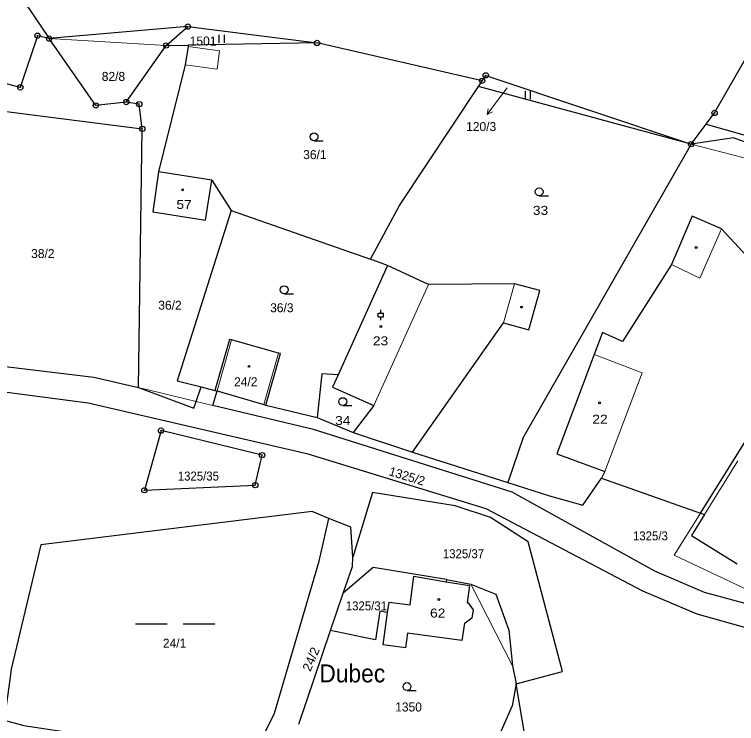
# Model space of a CAD drawing. Extents: x -872229 to -869198, y -1075981 to -1074329.
# Drawn here: x -871061.1 to -870924.3, y -1075218 to -1075083.8 of the extents above; entities that cross this region are included whole.
import ezdxf
from ezdxf.enums import TextEntityAlignment as Align

# ---------------------------------------------------------------- set-up
doc = ezdxf.new("R2010")
doc.units = 0
doc.header["$LTSCALE"] = 0.68
for name, color, linetype, lineweight in [('1', 7, 'Continuous', 25), ('3', 7, 'Continuous', 25), ('4', 7, 'Continuous', 13), ('5', 7, 'Continuous', 25), ('7', 7, 'Continuous', 13), ('8', 7, 'Continuous', 25)]:
    doc.layers.add(name, color=color, linetype=linetype, lineweight=lineweight)
doc.layers.add('2', color=7, linetype='Continuous')

msp = doc.modelspace()

# ---------------------------------------------------------------- linework, layer by layer
at = {"layer": '1'}
for p, q in [((-871028.23, -1075086.09), (-871054.49, -1075088.37)), ((-871028.23, -1075086.09), (-871003.76, -1075089.18)), ((-871032.34, -1075089.67), (-871028.14, -1075089.6)), ((-870932.92, -1075108.35), (-870973.2, -1075097.45)), ((-871023.7, -1075115.19), (-871033.76, -1075113.61)), ((-870990.4, -1075131.32), (-870993.62, -1075130.11)), ((-870990.4, -1075131.32), (-870999.76, -1075152)), ((-871023.09, -1075154.96), (-871022.7, -1075155.06)), ((-871013.43, -1075157.73), (-871003.73, -1075160.06)), ((-871003.73, -1075160.06), (-870996.9, -1075162.9)), ((-870985.66, -1075166.64), (-870967.62, -1075172.38)), ((-870979.23, -1075190.74), (-870979.29, -1075191.16))]:
    msp.add_line(p, q, dxfattribs=at)
for points in [[(-871096.99, -1075058.79), (-871086.45, -1075041.13), (-871054.49, -1075088.37)], [(-870930.06, -1075104.56), (-870928.47, -1075102.44), (-870911.59, -1075072.86)], [(-871039.89, -1075100.38), (-871032.34, -1075089.67), (-871028.23, -1075086.09)], [(-871054.49, -1075088.37), (-871056.71, -1075087.82), (-871059.95, -1075097.6), (-871082.7, -1075091.52), (-871084.87, -1075101.96), (-871097.87, -1075101.74), (-871098.57, -1075150.11)], [(-871039.89, -1075100.38), (-871045.65, -1075101.02), (-871054.49, -1075088.37)], [(-870930.06, -1075104.56), (-870893.7, -1075114.82), (-870892.44, -1075115.73), (-870873.52, -1075088.47)], [(-871028.14, -1075089.6), (-871028.19, -1075089.87), (-871028.73, -1075093.31), (-871033.76, -1075113.61)], [(-870993.62, -1075130.11), (-870988.12, -1075119.98), (-870973.2, -1075097.45), (-870972.48, -1075096.35), (-871003.76, -1075089.18), (-871028.14, -1075089.6)], [(-870972.48, -1075096.35), (-870971.82, -1075095.32), (-870932.92, -1075108.35), (-870930.06, -1075104.56)], [(-871036.85, -1075105.44), (-871037.42, -1075100.77), (-871039.89, -1075100.38)], [(-871079.42, -1075148.83), (-871066.59, -1075101.65), (-871036.85, -1075105.44)], [(-871079.42, -1075148.83), (-871062.25, -1075150.52), (-871046.01, -1075152.47), (-871037.58, -1075154.42), (-871036.85, -1075105.44)], [(-870894.66, -1075118.2), (-870924.88, -1075107.13), (-870932.92, -1075108.35)], [(-870932.92, -1075108.35), (-870964.73, -1075163.9), (-870967.62, -1075172.38)], [(-871033.76, -1075113.61), (-871034.87, -1075121.15), (-871024.86, -1075122.7), (-871023.7, -1075115.19)], [(-871023.7, -1075115.19), (-871020.03, -1075120.92), (-870993.62, -1075130.11)], [(-871020.03, -1075120.92), (-871030.27, -1075153.16), (-871025.72, -1075154.3), (-871023.09, -1075154.96)], [(-870909.44, -1075143.5), (-870927.17, -1075124.39), (-870932.72, -1075121.96), (-870936.66, -1075131.14), (-870945.89, -1075145.67), (-870949.71, -1075143.97), (-870951.3, -1075148.19), (-870958.37, -1075166.98), (-870949.29, -1075170.31), (-870949.89, -1075171.55)], [(-870985.66, -1075166.64), (-870968.48, -1075142.15), (-870963.66, -1075143.5), (-870961.56, -1075136.03), (-870966.35, -1075134.76), (-870982.63, -1075134.88), (-870990.4, -1075131.32)], [(-870949.89, -1075171.55), (-870931.15, -1075178.18), (-870909.44, -1075143.5)], [(-871013.43, -1075157.73), (-871010.7, -1075148), (-871011.09, -1075147.89), (-871019.98, -1075145.4), (-871020.37, -1075145.29), (-871023.09, -1075154.96)], [(-870999.76, -1075152), (-871002.87, -1075151.84), (-871003.73, -1075160.06)], [(-870999.76, -1075152), (-871000.82, -1075154.35), (-870993.02, -1075157.81), (-870996.9, -1075162.9), (-870985.66, -1075166.64)], [(-871037.58, -1075154.42), (-871027.08, -1075158.32), (-871026.66, -1075157.07), (-871025.72, -1075154.3)], [(-870920.27, -1075200.54), (-870931.8, -1075197.32), (-870942.08, -1075192.95), (-870971.72, -1075177.36), (-871005.41, -1075167.04), (-871047.1, -1075157.35), (-871062.52, -1075155.35), (-871102.88, -1075157.06), (-871104.75, -1075159), (-871097.61, -1075176.34), (-871085.24, -1075203.86)], [(-870890.21, -1075195.64), (-870895.9, -1075197.55), (-870905.34, -1075198.25), (-870918.98, -1075196.32), (-870930.4, -1075193.2), (-870939.76, -1075189.14), (-870966.78, -1075174.22), (-871004.43, -1075162.38), (-871023.49, -1075157.84), (-871022.7, -1075155.06)], [(-871022.7, -1075155.06), (-871013.81, -1075157.61), (-871013.43, -1075157.73)], [(-870967.62, -1075172.38), (-870959.73, -1075174.93), (-870953.43, -1075176.66), (-870949.89, -1075171.55)], [(-870966.06, -1075210.48), (-870957.3, -1075208.15), (-870963.76, -1075183.6), (-870970.92, -1075179.02), (-870977.61, -1075176.79), (-870993.24, -1075174.31), (-870997.01, -1075186.5)], [(-871001.53, -1075179.18), (-871004.71, -1075177.87), (-871056.06, -1075184.2), (-871061.68, -1075207.72), (-871062.03, -1075210.19), (-871063.04, -1075217.35), (-871059.26, -1075218.39), (-871047.62, -1075220.14), (-871017.06, -1075226.57)], [(-870931.15, -1075178.18), (-870930.37, -1075178.46), (-870932.82, -1075182.43), (-870924.17, -1075187.79)], [(-871017.06, -1075226.57), (-871011.81, -1075216.07), (-871003.35, -1075187.3), (-871001.53, -1075179.18)], [(-870997.01, -1075186.5), (-870997.37, -1075180.84), (-871001.53, -1075179.18)], [(-870998.8, -1075193.31), (-870997.07, -1075188.28), (-870997.01, -1075186.5)], [(-870979.23, -1075190.74), (-870993.12, -1075188.48), (-870998.8, -1075193.31)], [(-870979.29, -1075191.16), (-870974.87, -1075191.89), (-870975.32, -1075195.16), (-870975.14, -1075195.19), (-870974.22, -1075196.48), (-870974.46, -1075198.06), (-870975.68, -1075199.03), (-870975.85, -1075199.01), (-870976.31, -1075202.31), (-870986.61, -1075200.89), (-870987, -1075203.71), (-870991.24, -1075203.13), (-870990.39, -1075196.98)], [(-870990.39, -1075196.98), (-870990.12, -1075195.01), (-870986.15, -1075195.56), (-870985.45, -1075190.14), (-870979.29, -1075191.16)], [(-870979.23, -1075190.74), (-870974.62, -1075191.6), (-870969.92, -1075193.54), (-870967.43, -1075200.31), (-870966.72, -1075207.08), (-870966.06, -1075210.48)], [(-871007.2, -1075218.13), (-871001.24, -1075200.4), (-870998.8, -1075193.31)], [(-870990.39, -1075196.98), (-870991.87, -1075196.75), (-870992.71, -1075202.14), (-870995.21, -1075201.67), (-871001.24, -1075200.4)], [(-871003.22, -1075237.41), (-870964.99, -1075251.33), (-870962.5, -1075231.49), (-870966.06, -1075210.48)], [(-870966.06, -1075210.48), (-870966.78, -1075214.64), (-870977.55, -1075238.93), (-870992.35, -1075240.01), (-871003.22, -1075237.41)]]:
    msp.add_lwpolyline(points, dxfattribs=at)
msp.add_lwpolyline([(-871014.17, -1075167.21), (-871033.31, -1075162.57), (-871036.46, -1075173.85), (-871015.46, -1075172.89)], close=True, dxfattribs=at)
at = {"layer": '3'}
for p, q in [((-871022.281, -1075089.17), (-871022.281, -1075087.67)), ((-871021.28, -1075089.17), (-871021.28, -1075087.67)), ((-870964.311, -1075099.81), (-870964.311, -1075098.31)), ((-870963.31, -1075099.81), (-870963.31, -1075098.31)), ((-871004.333, -1075107.71), (-871002.583, -1075107.71)), ((-870961.693, -1075118.12), (-870959.943, -1075118.12)), ((-871009.983, -1075136.66), (-871008.233, -1075136.66)), ((-870992.183, -1075140.351), (-870991.177, -1075140.351)), ((-870992.183, -1075141.022), (-870992.183, -1075140.351)), ((-870991.68, -1075140.351), (-870991.68, -1075139.68)), ((-870991.177, -1075141.022), (-870991.177, -1075140.351)), ((-870992.183, -1075141.022), (-870991.177, -1075141.022)), ((-870991.68, -1075141.69), (-870991.68, -1075141.022)), ((-870998.893, -1075157.83), (-870997.143, -1075157.83)), ((-871038.139, -1075199.16), (-871032.139, -1075199.16)), ((-871029.139, -1075199.16), (-871023.139, -1075199.16)), ((-870986.723, -1075211.76), (-870984.973, -1075211.76))]:
    msp.add_line(p, q, dxfattribs=at)
for centre in [(-871004.3329, -1075106.9598), (-870961.6929, -1075117.3698), (-871009.9829, -1075135.9098), (-870998.8929, -1075157.0798), (-870986.7229, -1075211.0098)]:
    msp.add_circle(centre, 0.75, dxfattribs=at)
at = {"layer": '4'}
for p, q in [((-871054.49, -1075088.37), (-871032.34, -1075089.67)), ((-871028.19, -1075089.87), (-871022.21, -1075090.7)), ((-871022.67, -1075094.15), (-871022.21, -1075090.7)), ((-871028.73, -1075093.31), (-871022.67, -1075094.15)), ((-870932.92, -1075108.35), (-870894.66, -1075118.2)), ((-870931.26, -1075133.74), (-870927.17, -1075124.39)), ((-870936.66, -1075131.14), (-870931.26, -1075133.74)), ((-870993.02, -1075157.81), (-870982.63, -1075134.88)), ((-870968.48, -1075142.15), (-870966.35, -1075134.76)), ((-871022.7, -1075155.06), (-871019.98, -1075145.4)), ((-871013.81, -1075157.61), (-871011.09, -1075147.89)), ((-870951.3, -1075148.19), (-870942.22, -1075151.6)), ((-870949.29, -1075170.31), (-870942.22, -1075151.6)), ((-871037.58, -1075154.42), (-871026.66, -1075157.07)), ((-871026.66, -1075157.07), (-871023.49, -1075157.84)), ((-870930.37, -1075178.46), (-870924.07, -1075168.28)), ((-870936.12, -1075186.16), (-870931.15, -1075178.18)), ((-870936.12, -1075186.16), (-870919.45, -1075194.01)), ((-870974.62, -1075191.6), (-870966.72, -1075207.08))]:
    msp.add_line(p, q, dxfattribs=at)
at = {"layer": '5'}
for centre in [(-871029.2068, -1075116.9792), (-870931.9568, -1075127.9092), (-870965.0368, -1075139.1792), (-870991.6868, -1075142.8692), (-871016.6468, -1075150.4092), (-870950.2568, -1075157.3192), (-870980.6868, -1075194.5192)]:
    msp.add_circle(centre, 0.175, dxfattribs=at)
at = {"layer": '7'}
msp.add_line((-870971.556, -1075102.737), (-870970.553, -1075102.238), dxfattribs=at)
msp.add_lwpolyline([(-870967.73, -1075097.71), (-870969.75, -1075100.34), (-870971.556, -1075102.737), (-870971.353, -1075101.636)], dxfattribs=at)
at = {"layer": '8'}
for centre, radius in [((-871028.23, -1075086.0899), 0.5), ((-871028.23, -1075086.0899), 0.0303), ((-871056.71, -1075087.8199), 0.5), ((-871056.71, -1075087.8199), 0.0303), ((-871054.49, -1075088.3699), 0.5), ((-871054.49, -1075088.3699), 0.0303), ((-871003.76, -1075089.1799), 0.5), ((-871032.34, -1075089.6699), 0.5), ((-871032.34, -1075089.6699), 0.0303), ((-871003.76, -1075089.1799), 0.0303), ((-870971.82, -1075095.3199), 0.5), ((-870971.82, -1075095.3199), 0.0303), ((-870972.48, -1075096.3499), 0.5), ((-870972.48, -1075096.3499), 0.0303), ((-871059.95, -1075097.5999), 0.5), ((-871059.95, -1075097.5999), 0.0303), ((-871045.65, -1075101.0199), 0.5), ((-871045.65, -1075101.0199), 0.0303), ((-871039.89, -1075100.3799), 0.5), ((-871039.89, -1075100.3799), 0.0303), ((-871037.42, -1075100.7699), 0.5), ((-871037.42, -1075100.7699), 0.0303), ((-870928.47, -1075102.4399), 0.5), ((-870928.47, -1075102.4399), 0.0303), ((-871036.85, -1075105.4399), 0.5), ((-871036.85, -1075105.4399), 0.0303), ((-870932.92, -1075108.3499), 0.5), ((-870932.92, -1075108.3499), 0.0303), ((-871033.31, -1075162.5699), 0.5), ((-871033.31, -1075162.5699), 0.0303), ((-871014.17, -1075167.2099), 0.5), ((-871014.17, -1075167.2099), 0.0303), ((-871036.46, -1075173.8499), 0.5), ((-871015.46, -1075172.8899), 0.5), ((-871015.46, -1075172.8899), 0.0303), ((-871036.46, -1075173.8499), 0.0303)]:
    msp.add_circle(centre, radius, dxfattribs=at)

# ---------------------------------------------------------------- texts
at = {"layer": '2'}
for s, p in [('1501', (-871027.87, -1075089.67)), ('82/8', (-871044.53, -1075096.37)), ('36/1', (-871006.38, -1075111.17)), ('38/2', (-871057.9, -1075129.9)), ('36/2', (-871033.82, -1075139.68)), ('36/3', (-871012.64, -1075140.16)), ('24/2', (-871019.47, -1075154.17)), ('24/1', (-871032.95, -1075203.65)), ('1350', (-870988.96, -1075215.73))]:
    msp.add_text(s, height=1.7, dxfattribs=at).set_placement(p)
msp.add_text('120/3', height=1.7, dxfattribs=at).set_placement((-870972.68, -1075105.87), align=Align.CENTER)
for s, width, p in [('57', 1.15, (-871030.39, -1075120.6)), ('33', 1.15, (-870962.9, -1075121.73)), ('23', 1.15, (-870993.19, -1075146.42)), ('34', 1.15, (-871000.34, -1075161.51)), ('22', 1.15, (-870951.63, -1075161.25)), ('1325/35', 0.95, (-871030.14, -1075172.02)), ('1325/3', 0.95, (-870943.93, -1075183.34)), ('1325/37', 0.95, (-870979.93, -1075186.72)), ('1325/31', 0.95, (-870998.32, -1075196.59))]:
    msp.add_text(s, height=1.7, dxfattribs=dict(at, width=width)).set_placement(p)
msp.add_text('1325/2', height=1.7, rotation=343, dxfattribs=at).set_placement((-870990.298, -1075170.982))
at = {"layer": '2', "width": 1.15}
msp.add_text('62', height=1.7, dxfattribs=at).set_placement((-870980.91, -1075197.95), align=Align.CENTER)
at = {"layer": '2', "width": 1.05}
msp.add_text('24/2', height=1.7, rotation=67, dxfattribs=at).set_placement((-871005.027, -1075208.292))
at = {"layer": '7', "width": 0.95}
msp.add_text('Dubec', height=3.4, dxfattribs=at).set_placement((-870997.09, -1075210.22), align=Align.CENTER)

doc.saveas('drawing.dxf')
